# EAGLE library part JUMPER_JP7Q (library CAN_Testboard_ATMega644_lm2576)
JUMPER
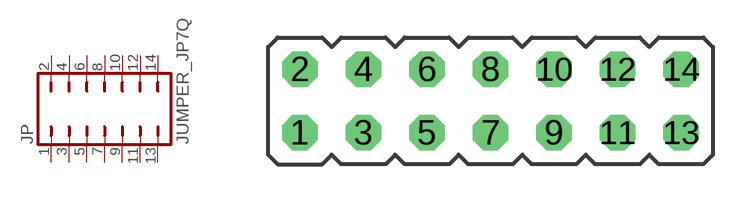
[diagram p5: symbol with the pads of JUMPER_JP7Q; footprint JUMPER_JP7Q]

Designator prefix JP

## JUMPER_JP7Q  [JUMPER_JP7Q]
1  1  pas
2  2  pas
3  3  pas
4  4  pas
5  5  pas
6  6  pas
7  7  pas
8  8  pas
9  9  pas
10  10  pas
11  11  pas
12  12  pas
13  13  pas
14  14  pas

## Footprint JUMPER_JP7Q (pad centres in mm)
JUMPER
drill 0.914 octagon: 1 -7.62,-1.27; 2 -7.62,1.27; 3 -5.08,-1.27; 4 -5.08,1.27; 5 -2.54,-1.27; 6 -2.54,1.27; 7 0,-1.27; 8 0,1.27; 9 2.54,-1.27; 10 2.54,1.27; 11 5.08,-1.27; 12 5.08,1.27; 13 7.62,-1.27; 14 7.62,1.27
